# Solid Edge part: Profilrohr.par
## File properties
Username: bmolnar
Dokumentum tartalom típus: 0
Author: bmolnar
Last saved by: bmolnar
Revision: 87
Sűrűség: 0,000 kg/m^3
Pontosság: 0,990
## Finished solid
Body 1: solid body, 115 faces, 338 edges, 224 vertices.
  Faces by surface: cylinder 59, plane 56
  Edges by curve: line 220, circle 118
Bounding box of the edges (mm): 95.500 x 95.500 x 104.000, from (-47.75, -47.75, -75) to (47.75, 47.75, 29).
Cylindrical faces by radius (mm): R0.2 x24, R0.5 x24, R1 x4, R10 x4, R13.5 x2, R40 x1
Planar faces by outward normal: +x 13, +y 14, +z 1, -x 13, -y 14, -z 1
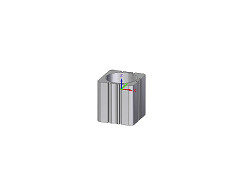
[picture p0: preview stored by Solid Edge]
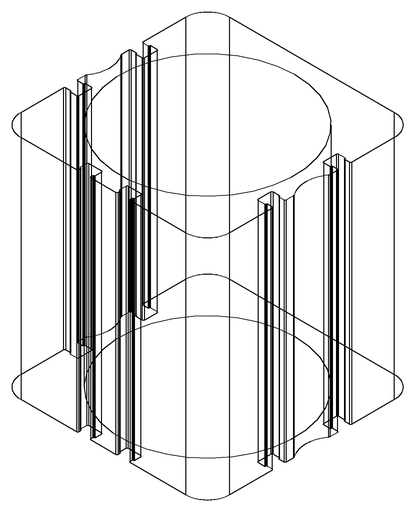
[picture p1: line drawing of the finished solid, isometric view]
